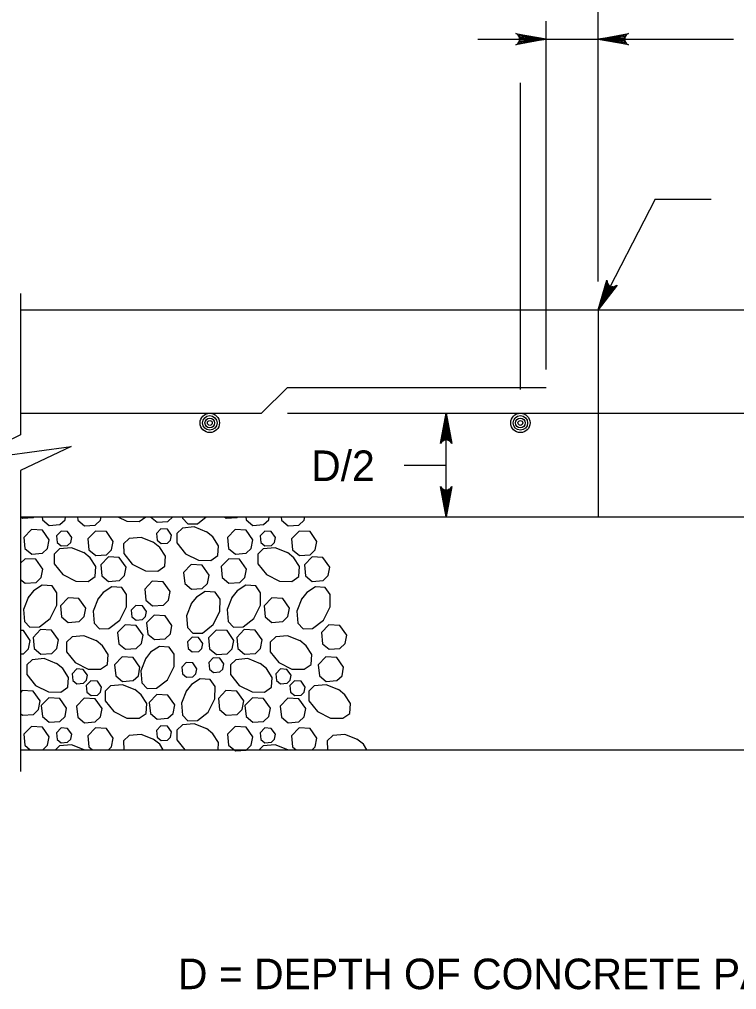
# Model space of a CAD drawing. Extents: x 2084213 to 2099800, y 976677 to 981262.
# Drawn here: x 2095516.1 to 2095747, y 979121.1 to 979433.4 of the extents above; entities that cross this region are included whole.
import ezdxf

# ---------------------------------------------------------------- set-up
doc = ezdxf.new("R2010")
doc.units = 0
doc.layers.add('1', color=7, linetype='Continuous')

msp = doc.modelspace()

# ---------------------------------------------------------------- linework, layer by layer
at = {"layer": '1'}
for p, q in [((2095702.37, 979349.08), (2095702.37, 979641.99)), ((2095685.7, 979320.72), (2095685.7, 979432.84)), ((2095663.63, 979427.06), (2095746.04, 979427.06)), ((2095677.37, 979314.25), (2095677.37, 979413.06)), ((2095720.72, 979375.58), (2095702.37, 979339.99)), ((2095720.72, 979375.58), (2095738.82, 979375.58)), ((2095516.44, 979345.18), (2095516.44, 979299.74)), ((2095516.44, 979339.99), (2095888.3, 979339.99)), ((2095702.37, 979339.99), (2095702.37, 979273.33)), ((2095602.37, 979314.99), (2095594.04, 979306.66)), ((2095602.37, 979314.99), (2095685.7, 979314.99)), ((2095516.61, 979306.66), (2095594.04, 979306.66)), ((2095602.37, 979306.66), (2095802.37, 979306.66)), ((2095653.46, 979273.33), (2095653.46, 979306.66)), ((2095653.46, 979289.81), (2095639.94, 979289.79)), ((2095516.44, 979288.2), (2095516.44, 979191.31)), ((2095516.44, 979273.33), (2095888.3, 979273.33)), ((2095516.44, 979198.33), (2095888.3, 979198.33))]:
    msp.add_line(p, q, dxfattribs=at)
for points in [[(2095685.7, 979427.06), (2095675.92, 979425.23), (2095676.29, 979425.49), (2095676.67, 979425.75), (2095676.86, 979426.08), (2095677.06, 979426.4), (2095677.11, 979426.73), (2095677.17, 979427.06), (2095677.11, 979427.39), (2095677.06, 979427.72), (2095676.86, 979428.04), (2095676.67, 979428.37), (2095676.29, 979428.63), (2095675.92, 979428.9), (2095685.7, 979427.06), (2095676.29, 979428.63), (2095676.67, 979428.37), (2095685.7, 979427.06), (2095676.86, 979428.04), (2095677.06, 979427.72), (2095685.7, 979427.06), (2095677.11, 979427.39), (2095677.17, 979427.06), (2095685.7, 979427.06), (2095677.11, 979426.73), (2095677.06, 979426.4), (2095685.7, 979427.06), (2095676.86, 979426.08), (2095676.67, 979425.75), (2095685.7, 979427.06), (2095676.29, 979425.49)], [(2095702.37, 979427.06), (2095712.16, 979428.9), (2095711.78, 979428.63), (2095711.4, 979428.37), (2095711.21, 979428.04), (2095711.01, 979427.72), (2095710.96, 979427.39), (2095710.9, 979427.06), (2095710.96, 979426.73), (2095711.01, 979426.4), (2095711.21, 979426.08), (2095711.4, 979425.75), (2095711.78, 979425.49), (2095712.16, 979425.23), (2095702.37, 979427.06), (2095711.78, 979425.49), (2095711.4, 979425.75), (2095702.37, 979427.06), (2095711.21, 979426.08), (2095711.01, 979426.4), (2095702.37, 979427.06), (2095710.96, 979426.73), (2095710.9, 979427.06), (2095702.37, 979427.06), (2095710.96, 979427.39), (2095711.01, 979427.72), (2095702.37, 979427.06), (2095711.21, 979428.04), (2095711.4, 979428.37), (2095702.37, 979427.06), (2095711.78, 979428.63)], [(2095702.37, 979339.99), (2095705.22, 979349.53), (2095705.28, 979349.07), (2095705.34, 979348.62), (2095705.54, 979348.29), (2095705.75, 979347.97), (2095706.01, 979347.77), (2095706.28, 979347.57), (2095706.6, 979347.47), (2095706.91, 979347.37), (2095707.29, 979347.39), (2095707.68, 979347.42), (2095708.08, 979347.63), (2095708.49, 979347.85), (2095702.37, 979339.99), (2095708.08, 979347.63), (2095707.68, 979347.42), (2095702.37, 979339.99), (2095707.29, 979347.39), (2095706.91, 979347.37), (2095702.37, 979339.99), (2095706.6, 979347.47), (2095706.28, 979347.57), (2095702.37, 979339.99), (2095706.01, 979347.77), (2095705.75, 979347.97), (2095702.37, 979339.99), (2095705.54, 979348.29), (2095705.34, 979348.62), (2095702.37, 979339.99), (2095705.28, 979349.07)], [(2095653.46, 979306.66), (2095655.3, 979296.87), (2095655.03, 979297.25), (2095654.77, 979297.63), (2095654.44, 979297.82), (2095654.12, 979298.02), (2095653.79, 979298.07), (2095653.46, 979298.13), (2095653.13, 979298.07), (2095652.8, 979298.02), (2095652.48, 979297.82), (2095652.15, 979297.63), (2095651.89, 979297.25), (2095651.63, 979296.87), (2095653.46, 979306.66), (2095651.89, 979297.25), (2095652.15, 979297.63), (2095653.46, 979306.66), (2095652.48, 979297.82), (2095652.8, 979298.02), (2095653.46, 979306.66), (2095653.13, 979298.07), (2095653.46, 979298.13), (2095653.46, 979306.66), (2095653.79, 979298.07), (2095654.12, 979298.02), (2095653.46, 979306.66), (2095654.44, 979297.82), (2095654.77, 979297.63), (2095653.46, 979306.66), (2095655.03, 979297.25)], [(2095516.44, 979299.74), (2095499.43, 979291.42), (2095532.72, 979295.94), (2095516.44, 979288.2)], [(2095653.46, 979273.33), (2095651.63, 979283.11), (2095651.89, 979282.74), (2095652.15, 979282.36), (2095652.48, 979282.17), (2095652.8, 979281.97), (2095653.13, 979281.91), (2095653.46, 979281.86), (2095653.79, 979281.91), (2095654.12, 979281.97), (2095654.44, 979282.17), (2095654.77, 979282.36), (2095655.03, 979282.74), (2095655.3, 979283.11), (2095653.46, 979273.33), (2095655.03, 979282.74), (2095654.77, 979282.36), (2095653.46, 979273.33), (2095654.44, 979282.17), (2095654.12, 979281.97), (2095653.46, 979273.33), (2095653.79, 979281.91), (2095653.46, 979281.86), (2095653.46, 979273.33), (2095653.13, 979281.91), (2095652.8, 979281.97), (2095653.46, 979273.33), (2095652.48, 979282.17), (2095652.15, 979282.36), (2095653.46, 979273.33), (2095651.89, 979282.74)], [(2095516.5, 979273.33), (2095517.08, 979272.85), (2095520.56, 979273.1), (2095520.8, 979273.33)], [(2095523.37, 979273.33), (2095523.46, 979272.35), (2095525.64, 979270.54), (2095529.12, 979270.8), (2095530.75, 979272.38), (2095530.93, 979273.33)], [(2095534.73, 979273.33), (2095534.84, 979272.22), (2095537.02, 979270.41), (2095540.49, 979270.67), (2095542.13, 979272.25), (2095542.34, 979273.33)], [(2095547.78, 979273.33), (2095550.65, 979271.89), (2095554.63, 979271.82), (2095556.75, 979273.33)], [(2095558.32, 979273.33), (2095560.42, 979271.58), (2095563.9, 979271.83), (2095565.44, 979273.33)], [(2095568.56, 979273.33), (2095568.6, 979272.86), (2095570.31, 979271.05), (2095573.39, 979271.11), (2095576.22, 979273.33)], [(2095582.08, 979273.33), (2095582.66, 979272.85), (2095586.14, 979273.1), (2095586.38, 979273.33)], [(2095588.94, 979273.33), (2095589.04, 979272.35), (2095591.22, 979270.54), (2095594.69, 979270.8), (2095596.33, 979272.38), (2095596.51, 979273.33)], [(2095600.31, 979273.33), (2095600.42, 979272.22), (2095602.6, 979270.41), (2095606.07, 979270.67), (2095607.71, 979272.25), (2095607.92, 979273.33)], [(2095525.67, 979265.89), (2095523.46, 979269.03), (2095519.94, 979269.23), (2095517.49, 979266.69), (2095517.85, 979263.14), (2095520.02, 979261.33), (2095523.5, 979261.58), (2095525.14, 979263.16), (2095525.67, 979265.89)], [(2095532.9, 979266.71), (2095531.57, 979268.59), (2095529.46, 979268.71), (2095527.99, 979267.18), (2095528.2, 979265.05), (2095529.51, 979263.97), (2095531.6, 979264.12), (2095532.58, 979265.07), (2095532.9, 979266.7)], [(2095546.28, 979265.41), (2095544.07, 979268.55), (2095540.55, 979268.75), (2095538.1, 979266.22), (2095538.46, 979262.66), (2095540.63, 979260.85), (2095544.11, 979261.1), (2095545.75, 979262.69), (2095546.28, 979265.41)], [(2095565.06, 979267.43), (2095563.74, 979269.31), (2095561.63, 979269.43), (2095560.16, 979267.91), (2095560.37, 979265.78), (2095561.68, 979264.69), (2095563.76, 979264.84), (2095564.74, 979265.79), (2095565.06, 979267.43)], [(2095576.45, 979268.4), (2095572.32, 979270.04), (2095568.53, 979269.71), (2095566.73, 979268), (2095566.79, 979264.92), (2095569.52, 979261.43), (2095573.75, 979259.31), (2095577.73, 979259.24), (2095579.97, 979260.84), (2095580.18, 979264.01), (2095578.36, 979266.85), (2095576.28, 979268.51)], [(2095591.25, 979265.89), (2095589.04, 979269.03), (2095585.52, 979269.23), (2095583.07, 979266.69), (2095583.43, 979263.14), (2095585.6, 979261.33), (2095589.08, 979261.58), (2095590.72, 979263.16), (2095591.25, 979265.89)], [(2095598.48, 979266.71), (2095597.15, 979268.59), (2095595.04, 979268.71), (2095593.57, 979267.18), (2095593.78, 979265.05), (2095595.09, 979263.97), (2095597.18, 979264.12), (2095598.16, 979265.07), (2095598.48, 979266.7)], [(2095611.86, 979265.41), (2095609.65, 979268.55), (2095606.13, 979268.75), (2095603.68, 979266.22), (2095604.04, 979262.66), (2095606.21, 979260.85), (2095609.69, 979261.1), (2095611.33, 979262.69), (2095611.86, 979265.41)], [(2095559.35, 979265.01), (2095555.22, 979266.65), (2095551.43, 979266.32), (2095549.63, 979264.61), (2095549.69, 979261.53), (2095552.42, 979258.04), (2095556.65, 979255.93), (2095560.63, 979255.86), (2095562.87, 979257.45), (2095563.08, 979260.62), (2095561.26, 979263.46), (2095559.18, 979265.12)], [(2095536.93, 979261.68), (2095532.81, 979263.31), (2095529.02, 979262.99), (2095527.21, 979261.27), (2095527.27, 979258.2), (2095530.01, 979254.7), (2095534.23, 979252.59), (2095538.21, 979252.52), (2095540.46, 979254.11), (2095540.67, 979257.29), (2095538.85, 979260.12), (2095536.76, 979261.78)], [(2095602.51, 979261.68), (2095598.39, 979263.31), (2095594.59, 979262.99), (2095592.79, 979261.27), (2095592.85, 979258.2), (2095595.58, 979254.7), (2095599.81, 979252.59), (2095603.79, 979252.52), (2095606.03, 979254.11), (2095606.25, 979257.29), (2095604.43, 979260.12), (2095602.34, 979261.78)], [(2095523.59, 979256.5), (2095521.39, 979259.64), (2095517.87, 979259.84), (2095516.44, 979258.36)], [(2095550.43, 979257.11), (2095548.22, 979260.25), (2095544.7, 979260.45), (2095542.25, 979257.91), (2095542.61, 979254.36), (2095544.78, 979252.55), (2095548.26, 979252.8), (2095549.9, 979254.39), (2095550.43, 979257.11)], [(2095589.17, 979256.5), (2095586.97, 979259.64), (2095583.45, 979259.84), (2095581, 979257.3), (2095581.35, 979253.74), (2095583.53, 979251.93), (2095587, 979252.18), (2095588.64, 979253.77), (2095589.17, 979256.5)], [(2095616.01, 979257.11), (2095613.8, 979260.25), (2095610.28, 979260.45), (2095607.83, 979257.91), (2095608.19, 979254.36), (2095610.36, 979252.55), (2095613.84, 979252.8), (2095615.48, 979254.39), (2095616.01, 979257.11)], [(2095516.44, 979253.19), (2095517.95, 979251.93), (2095521.42, 979252.18), (2095523.06, 979253.77), (2095523.59, 979256.5)], [(2095577.11, 979254.58), (2095574.91, 979257.71), (2095571.39, 979257.92), (2095568.94, 979255.38), (2095569.29, 979251.82), (2095571.47, 979250.01), (2095574.95, 979250.26), (2095576.58, 979251.85), (2095577.11, 979254.58)], [(2095564.57, 979249.24), (2095562.37, 979252.38), (2095558.85, 979252.58), (2095556.4, 979250.04), (2095556.75, 979246.49), (2095558.93, 979244.68), (2095562.41, 979244.93), (2095564.04, 979246.52), (2095564.57, 979249.24)], [(2095519, 979247.56), (2095517.37, 979243.43), (2095517.7, 979239.64), (2095519.41, 979237.84), (2095522.48, 979237.9), (2095525.98, 979240.63), (2095528.09, 979244.86), (2095528.16, 979248.84), (2095526.57, 979251.08), (2095523.4, 979251.3), (2095520.56, 979249.48), (2095518.9, 979247.39)], [(2095541.42, 979247.03), (2095539.78, 979242.9), (2095540.11, 979239.11), (2095541.83, 979237.31), (2095544.9, 979237.37), (2095548.39, 979240.1), (2095550.51, 979244.33), (2095550.58, 979248.31), (2095548.99, 979250.55), (2095545.81, 979250.76), (2095542.98, 979248.94), (2095541.31, 979246.86)], [(2095571.51, 979245.56), (2095569.87, 979241.43), (2095570.2, 979237.64), (2095571.91, 979235.84), (2095574.99, 979235.9), (2095578.48, 979238.63), (2095580.59, 979242.86), (2095580.66, 979246.84), (2095579.07, 979249.08), (2095575.9, 979249.29), (2095573.06, 979247.48), (2095571.4, 979245.39)], [(2095584.58, 979247.56), (2095582.95, 979243.43), (2095583.28, 979239.64), (2095584.99, 979237.84), (2095588.06, 979237.9), (2095591.56, 979240.63), (2095593.67, 979244.86), (2095593.74, 979248.84), (2095592.15, 979251.08), (2095588.98, 979251.3), (2095586.14, 979249.48), (2095584.48, 979247.39)], [(2095607, 979247.03), (2095605.36, 979242.9), (2095605.69, 979239.11), (2095607.4, 979237.31), (2095610.48, 979237.37), (2095613.97, 979240.1), (2095616.09, 979244.33), (2095616.16, 979248.31), (2095614.56, 979250.55), (2095611.39, 979250.76), (2095608.56, 979248.94), (2095606.89, 979246.86)], [(2095537.46, 979243.91), (2095535.25, 979247.04), (2095531.73, 979247.24), (2095529.28, 979244.71), (2095529.64, 979241.15), (2095531.81, 979239.34), (2095535.29, 979239.59), (2095536.93, 979241.18), (2095537.46, 979243.91)], [(2095603.04, 979243.91), (2095600.83, 979247.04), (2095597.31, 979247.24), (2095594.86, 979244.71), (2095595.22, 979241.15), (2095597.39, 979239.34), (2095600.87, 979239.59), (2095602.5, 979241.18), (2095603.04, 979243.91)], [(2095557, 979242.81), (2095555.67, 979244.7), (2095553.56, 979244.82), (2095552.09, 979243.29), (2095552.3, 979241.16), (2095553.61, 979240.07), (2095555.69, 979240.23), (2095556.68, 979241.18), (2095556.99, 979242.81)], [(2095565.19, 979238.35), (2095562.99, 979241.48), (2095559.46, 979241.69), (2095557.02, 979239.15), (2095557.37, 979235.59), (2095559.55, 979233.78), (2095563.02, 979234.03), (2095564.66, 979235.62), (2095565.19, 979238.35)], [(2095519.56, 979233.54), (2095517.35, 979236.68), (2095516.44, 979236.73)], [(2095528.63, 979233.68), (2095526.43, 979236.82), (2095522.9, 979237.02), (2095520.46, 979234.48), (2095520.81, 979230.92), (2095522.99, 979229.11), (2095526.46, 979229.36), (2095528.1, 979230.95), (2095528.63, 979233.68)], [(2095555.87, 979235.23), (2095553.67, 979238.37), (2095550.15, 979238.57), (2095547.7, 979236.03), (2095548.05, 979232.48), (2095550.23, 979230.67), (2095553.7, 979230.92), (2095555.34, 979232.5), (2095555.87, 979235.23)], [(2095585.14, 979233.54), (2095582.93, 979236.68), (2095579.41, 979236.88), (2095576.96, 979234.34), (2095577.32, 979230.79), (2095579.49, 979228.98), (2095582.97, 979229.23), (2095584.6, 979230.82), (2095585.14, 979233.54)], [(2095594.21, 979233.68), (2095592.01, 979236.82), (2095588.48, 979237.02), (2095586.04, 979234.48), (2095586.39, 979230.92), (2095588.57, 979229.11), (2095592.04, 979229.36), (2095593.68, 979230.95), (2095594.21, 979233.68)], [(2095621.45, 979235.23), (2095619.24, 979238.37), (2095615.72, 979238.57), (2095613.28, 979236.03), (2095613.63, 979232.48), (2095615.8, 979230.67), (2095619.28, 979230.92), (2095620.92, 979232.5), (2095621.45, 979235.23)], [(2095516.44, 979229.16), (2095517.39, 979229.23), (2095519.02, 979230.82), (2095519.56, 979233.54)], [(2095540.93, 979233.39), (2095536.81, 979235.03), (2095533.02, 979234.7), (2095531.22, 979232.99), (2095531.27, 979229.91), (2095534.01, 979226.42), (2095538.23, 979224.3), (2095542.22, 979224.23), (2095544.46, 979225.83), (2095544.67, 979229), (2095542.85, 979231.83), (2095540.77, 979233.5)], [(2095575.1, 979232.58), (2095573.78, 979234.46), (2095571.66, 979234.58), (2095570.2, 979233.05), (2095570.41, 979230.92), (2095571.71, 979229.84), (2095573.8, 979229.99), (2095574.78, 979230.94), (2095575.1, 979232.57)], [(2095606.51, 979233.39), (2095602.39, 979235.03), (2095598.6, 979234.7), (2095596.8, 979232.99), (2095596.85, 979229.91), (2095599.59, 979226.42), (2095603.81, 979224.3), (2095607.79, 979224.23), (2095610.04, 979225.83), (2095610.25, 979229), (2095608.43, 979231.83), (2095606.35, 979233.5)], [(2095556.77, 979227.81), (2095555.13, 979223.69), (2095555.46, 979219.9), (2095557.17, 979218.1), (2095560.25, 979218.15), (2095563.74, 979220.89), (2095565.85, 979225.11), (2095565.92, 979229.09), (2095564.33, 979231.34), (2095561.16, 979231.55), (2095558.32, 979229.73), (2095556.66, 979227.65)], [(2095528.13, 979226.02), (2095524.01, 979227.66), (2095520.22, 979227.33), (2095518.41, 979225.62), (2095518.47, 979222.54), (2095521.21, 979219.04), (2095525.43, 979216.93), (2095529.41, 979216.86), (2095531.66, 979218.45), (2095531.87, 979221.63), (2095530.05, 979224.46), (2095527.97, 979226.13)], [(2095554.89, 979224.91), (2095552.68, 979228.05), (2095549.16, 979228.25), (2095546.72, 979225.71), (2095547.07, 979222.15), (2095549.24, 979220.34), (2095552.72, 979220.6), (2095554.36, 979222.18), (2095554.89, 979224.91)], [(2095581.93, 979225.95), (2095580.6, 979227.84), (2095578.49, 979227.96), (2095577.02, 979226.44), (2095577.24, 979224.3), (2095578.54, 979223.22), (2095580.63, 979223.37), (2095581.61, 979224.32), (2095581.93, 979225.95)], [(2095593.71, 979226.02), (2095589.59, 979227.66), (2095585.8, 979227.33), (2095583.99, 979225.62), (2095584.05, 979222.54), (2095586.79, 979219.04), (2095591.01, 979216.93), (2095594.99, 979216.86), (2095597.24, 979218.45), (2095597.45, 979221.63), (2095595.63, 979224.46), (2095593.55, 979226.13)], [(2095620.47, 979224.91), (2095618.26, 979228.05), (2095614.74, 979228.25), (2095612.29, 979225.71), (2095612.65, 979222.15), (2095614.82, 979220.34), (2095618.3, 979220.6), (2095619.94, 979222.18), (2095620.47, 979224.91)], [(2095537.97, 979222.34), (2095536.64, 979224.22), (2095534.53, 979224.34), (2095533.06, 979222.82), (2095533.27, 979220.68), (2095534.58, 979219.6), (2095536.66, 979219.75), (2095537.65, 979220.7), (2095537.96, 979222.34)], [(2095573.24, 979224.4), (2095571.92, 979226.29), (2095569.8, 979226.41), (2095568.33, 979224.88), (2095568.55, 979222.75), (2095569.85, 979221.66), (2095571.94, 979221.82), (2095572.92, 979222.77), (2095573.24, 979224.4)], [(2095603.54, 979222.34), (2095602.22, 979224.22), (2095600.11, 979224.34), (2095598.64, 979222.82), (2095598.85, 979220.68), (2095600.16, 979219.6), (2095602.24, 979219.75), (2095603.22, 979220.7), (2095603.54, 979222.34)], [(2095569.91, 979217.4), (2095568.27, 979213.28), (2095568.6, 979209.49), (2095570.31, 979207.69), (2095573.39, 979207.74), (2095576.88, 979210.48), (2095578.99, 979214.7), (2095579.06, 979218.69), (2095577.47, 979220.93), (2095574.3, 979221.14), (2095571.46, 979219.32), (2095569.8, 979217.24)], [(2095542.52, 979218.51), (2095541.19, 979220.39), (2095539.08, 979220.51), (2095537.61, 979218.99), (2095537.82, 979216.86), (2095539.13, 979215.77), (2095541.21, 979215.92), (2095542.2, 979216.87), (2095542.51, 979218.51)], [(2095553.35, 979217.61), (2095549.22, 979219.25), (2095545.43, 979218.92), (2095543.63, 979217.21), (2095543.69, 979214.13), (2095546.42, 979210.64), (2095550.65, 979208.53), (2095554.63, 979208.46), (2095556.87, 979210.05), (2095557.08, 979213.22), (2095555.27, 979216.06), (2095553.18, 979217.72)], [(2095608.09, 979218.51), (2095606.77, 979220.39), (2095604.66, 979220.51), (2095603.19, 979218.99), (2095603.4, 979216.86), (2095604.71, 979215.77), (2095606.79, 979215.92), (2095607.77, 979216.87), (2095608.09, 979218.51)], [(2095618.93, 979217.61), (2095614.8, 979219.25), (2095611.01, 979218.92), (2095609.21, 979217.21), (2095609.27, 979214.13), (2095612, 979210.64), (2095616.23, 979208.53), (2095620.21, 979208.46), (2095622.45, 979210.05), (2095622.66, 979213.22), (2095620.84, 979216.06), (2095618.76, 979217.72)], [(2095522.73, 979214.04), (2095520.52, 979217.18), (2095517, 979217.38), (2095516.44, 979216.8)], [(2095531.28, 979211.74), (2095529.08, 979214.88), (2095525.56, 979215.08), (2095523.11, 979212.54), (2095523.46, 979208.99), (2095525.64, 979207.18), (2095529.12, 979207.43), (2095530.75, 979209.02), (2095531.28, 979211.74)], [(2095542.66, 979211.61), (2095540.46, 979214.75), (2095536.93, 979214.95), (2095534.49, 979212.41), (2095534.84, 979208.86), (2095537.02, 979207.05), (2095540.49, 979207.3), (2095542.13, 979208.89), (2095542.66, 979211.61)], [(2095566.07, 979212.78), (2095563.86, 979215.92), (2095560.34, 979216.12), (2095557.89, 979213.58), (2095558.25, 979210.02), (2095560.42, 979208.21), (2095563.9, 979208.46), (2095565.54, 979210.05), (2095566.07, 979212.78)], [(2095588.31, 979214.04), (2095586.1, 979217.18), (2095582.58, 979217.38), (2095580.13, 979214.84), (2095580.49, 979211.29), (2095582.66, 979209.48), (2095586.14, 979209.73), (2095587.77, 979211.32), (2095588.31, 979214.04)], [(2095596.86, 979211.74), (2095594.66, 979214.88), (2095591.13, 979215.08), (2095588.69, 979212.54), (2095589.04, 979208.99), (2095591.22, 979207.18), (2095594.69, 979207.43), (2095596.33, 979209.02), (2095596.86, 979211.74)], [(2095608.24, 979211.61), (2095606.04, 979214.75), (2095602.51, 979214.95), (2095600.07, 979212.41), (2095600.42, 979208.86), (2095602.6, 979207.05), (2095606.07, 979207.3), (2095607.71, 979208.89), (2095608.24, 979211.61)], [(2095516.44, 979210.01), (2095517.08, 979209.48), (2095520.56, 979209.73), (2095522.2, 979211.32), (2095522.73, 979214.04)], [(2095525.67, 979202.52), (2095523.46, 979205.66), (2095519.94, 979205.86), (2095517.49, 979203.33), (2095517.85, 979199.77), (2095519.58, 979198.33)], [(2095532.9, 979203.34), (2095531.57, 979205.22), (2095529.46, 979205.34), (2095527.99, 979203.82), (2095528.2, 979201.68), (2095529.51, 979200.6), (2095531.6, 979200.75), (2095532.58, 979201.7), (2095532.9, 979203.34)], [(2095546.28, 979202.05), (2095544.07, 979205.19), (2095540.55, 979205.39), (2095538.1, 979202.85), (2095538.46, 979199.29), (2095539.62, 979198.33)], [(2095565.06, 979204.06), (2095563.74, 979205.94), (2095561.63, 979206.06), (2095560.16, 979204.54), (2095560.37, 979202.41), (2095561.68, 979201.32), (2095563.76, 979201.47), (2095564.74, 979202.43), (2095565.06, 979204.06)], [(2095576.45, 979205.03), (2095572.32, 979206.67), (2095568.53, 979206.34), (2095566.73, 979204.63), (2095566.79, 979201.55), (2095569.31, 979198.33)], [(2095591.25, 979202.52), (2095589.04, 979205.66), (2095585.52, 979205.86), (2095583.07, 979203.33), (2095583.43, 979199.77), (2095585.6, 979197.96), (2095589.08, 979198.21), (2095590.72, 979199.8), (2095591.25, 979202.52)], [(2095598.48, 979203.34), (2095597.15, 979205.22), (2095595.04, 979205.34), (2095593.57, 979203.82), (2095593.78, 979201.68), (2095595.09, 979200.6), (2095597.18, 979200.75), (2095598.16, 979201.7), (2095598.48, 979203.34)], [(2095611.86, 979202.05), (2095609.65, 979205.19), (2095606.13, 979205.39), (2095603.68, 979202.85), (2095604.04, 979199.29), (2095605.2, 979198.33)], [(2095523.62, 979198.33), (2095525.14, 979199.8), (2095525.67, 979202.52)], [(2095544.72, 979198.33), (2095545.75, 979199.32), (2095546.28, 979202.05)], [(2095559.35, 979201.65), (2095555.22, 979203.28), (2095551.43, 979202.95), (2095549.63, 979201.24), (2095549.68, 979198.33)], [(2095580.03, 979198.33), (2095580.18, 979200.64), (2095578.36, 979203.48), (2095576.28, 979205.14)], [(2095610.3, 979198.33), (2095611.33, 979199.32), (2095611.86, 979202.05)], [(2095624.93, 979201.65), (2095620.8, 979203.28), (2095617.01, 979202.95), (2095615.21, 979201.24), (2095615.26, 979198.33)], [(2095536.89, 979198.33), (2095532.81, 979199.95), (2095529.02, 979199.62), (2095527.66, 979198.33)], [(2095562.39, 979198.33), (2095561.26, 979200.09), (2095559.18, 979201.75)], [(2095602.51, 979198.31), (2095598.39, 979199.95), (2095594.59, 979199.62), (2095593.24, 979198.33)], [(2095627.97, 979198.33), (2095626.84, 979200.09), (2095624.76, 979201.75)], [(2095536.87, 979198.33), (2095536.76, 979198.42)], [(2095536.88, 979198.33), (2095536.77, 979198.42)], [(2095602.45, 979198.33), (2095602.34, 979198.42)]]:
    msp.add_lwpolyline(points, dxfattribs=at)
for centre, radius in [((2095577.37, 979303.54), 3.12), ((2095577.37, 979303.54), 2.34), ((2095677.37, 979303.54), 3.12), ((2095677.37, 979303.54), 2.34), ((2095577.37, 979303.54), 1.56), ((2095577.37, 979303.54), 0.781), ((2095677.37, 979303.54), 1.56), ((2095677.37, 979303.54), 0.781)]:
    msp.add_circle(centre, radius, dxfattribs=at)

# ---------------------------------------------------------------- texts
for s, height, p in [('D/2', 9.843, (2095610, 979284.83)), ('D = DEPTH OF CONCRETE PAVEMENT', 9.8425, (2095567.12, 979121.27))]:
    msp.add_text(s, height=height, dxfattribs=at).set_placement(p)

doc.saveas('drawing.dxf')
